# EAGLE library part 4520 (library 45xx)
Dual binary up COUNTER
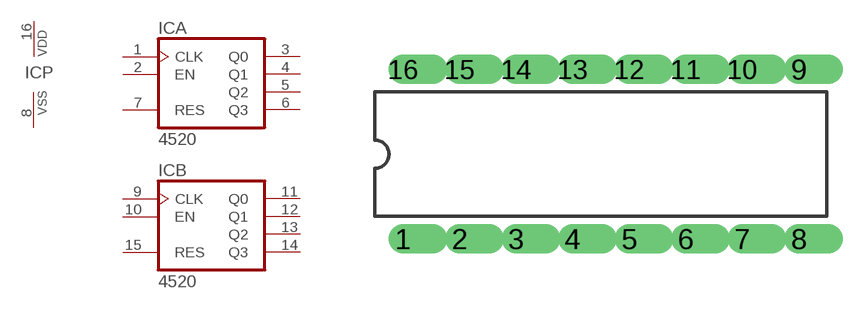
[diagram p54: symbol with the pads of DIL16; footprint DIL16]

Designator prefix IC; gates A=4518 B=4518 P=PWRN

## 4520N  [DIL16]
1  A:CLK  in
2  A:EN  in
3  A:Q0  out
4  A:Q1  out
5  A:Q2  out
6  A:Q3  out
7  A:RES  in
8  P:VSS  pwr
9  B:CLK  in
10  B:EN  in
11  B:Q0  out
12  B:Q1  out
13  B:Q2  out
14  B:Q3  out
15  B:RES  in
16  P:VDD  pwr

## Footprint DIL16 (pad centres in mm)
Dual In Line
drill 0.813 offset: 1 -8.89,-3.81; 2 -6.35,-3.81; 3 -3.81,-3.81; 4 -1.27,-3.81; 5 1.27,-3.81; 6 3.81,-3.81; 7 6.35,-3.81; 8 8.89,-3.81; 9 8.89,3.81; 10 6.35,3.81; 11 3.81,3.81; 12 1.27,3.81; 13 -1.27,3.81; 14 -3.81,3.81; 15 -6.35,3.81; 16 -8.89,3.81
